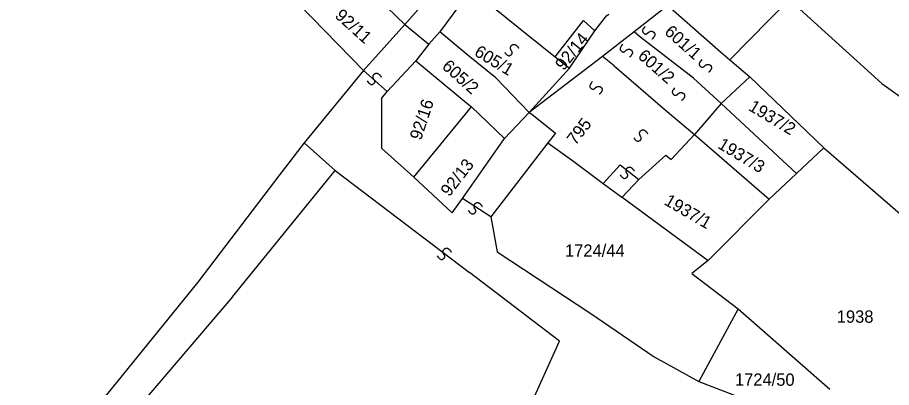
# Model space of a CAD drawing. Extents: x -581999 to -572728, y -1219553 to -1212032.
# Drawn here: x -578202.6 to -578061, y -1216054.7 to -1215994.7 of the extents above; entities that cross this region are included whole.
import ezdxf

# ---------------------------------------------------------------- set-up
doc = ezdxf.new("R2010")
doc.units = 0
for name, color, linetype in [('Vrstva 1', 7, 'Continuous'), ('Vrstva 2', 7, 'Continuous'), ('Vrstva 4', 7, 'Continuous'), ('Vrstva 6', 7, 'Continuous')]:
    doc.layers.add(name, color=color, linetype=linetype)

msp = doc.modelspace()

# ---------------------------------------------------------------- linework, layer by layer
at = {"layer": 'Vrstva 1'}
for p, q in [((-578139.851, -1215995.835), (-578135.956, -1215999.052)), ((-578115.453, -1216001.107), (-578110.864, -1215995.222)), ((-578110.864, -1215995.222), (-578109.045, -1215996.864)), ((-578101.772, -1215997.776), (-578102.681, -1215997.046)), ((-578093.044, -1216004.524), (-578101.772, -1215997.776)), ((-578116.469, -1216000.271), (-578115.453, -1216001.107)), ((-578115.453, -1216001.107), (-578113.167, -1216002.916)), ((-578105.92, -1216002.564), (-578107.772, -1216001.058)), ((-578088.547, -1216008.672), (-578093.044, -1216004.524)), ((-578119.665, -1216010.091), (-578119.228, -1216010.36)), ((-578119.228, -1216010.36), (-578115.409, -1216013.46)), ((-578115.409, -1216013.46), (-578116.637, -1216015.015)), ((-578151.137, -1216019.51), (-578156.158, -1216015.046)), ((-578116.637, -1216015.015), (-578113.054, -1216017.591)), ((-578076.346, -1216020.003), (-578071.932, -1216015.841)), ((-578113.054, -1216017.591), (-578112.637, -1216017.906)), ((-578112.637, -1216017.906), (-578107.7, -1216021.639)), ((-578167.767, -1216039.989), (-578151.137, -1216019.51)), ((-578080.759, -1216024.165), (-578076.346, -1216020.003))]:
    msp.add_line(p, q, dxfattribs=at)
for points in [[(-578129.074, -1215990.135), (-578134.141, -1215997.026)], [(-578136.492, -1215992.089), (-578139.851, -1215995.835)], [(-578126.956, -1215991.811), (-578121.41, -1215996.317), (-578116.469, -1216000.271)], [(-578077.566, -1215991.739), (-578087.158, -1216001.569)], [(-578077.566, -1215991.739), (-578062.548, -1216005.425), (-578049.109, -1216014.994)], [(-578146.526, -1216003.285), (-578157.002, -1215992.533)], [(-578097.19, -1215992.761), (-578102.681, -1215997.046), (-578107.772, -1216001.058), (-578119.665, -1216010.091)], [(-578097.19, -1215992.761), (-578088.663, -1216000.298)], [(-578113.167, -1216002.916), (-578109.045, -1215996.864), (-578107.154, -1215994.417), (-578106.766, -1215994.197)], [(-578139.851, -1215995.835), (-578146.526, -1216003.285)], [(-578134.141, -1215997.026), (-578135.956, -1215999.052), (-578138.064, -1216001.737)], [(-578129.569, -1216000.867), (-578134.141, -1215997.026)], [(-578088.663, -1216000.298), (-578087.158, -1216001.569)], [(-578143.599, -1216007.848), (-578142.684, -1216006.712), (-578138.064, -1216001.737)], [(-578138.064, -1216001.737), (-578129.492, -1216008.808)], [(-578125.094, -1216004.515), (-578129.569, -1216000.867)], [(-578087.158, -1216001.569), (-578083.919, -1216004.303)], [(-578146.526, -1216003.285), (-578156.158, -1216015.046), (-578160.105, -1216020.168), (-578173.391, -1216037.585)], [(-578119.665, -1216010.091), (-578113.167, -1216002.916)], [(-578105.92, -1216002.564), (-578097.627, -1216009.683)], [(-578125.094, -1216004.515), (-578119.665, -1216010.091)], [(-578083.919, -1216004.303), (-578088.547, -1216008.672)], [(-578083.919, -1216004.303), (-578071.932, -1216015.841)], [(-578143.599, -1216007.848), (-578143.612, -1216015.897), (-578138.374, -1216020.6)], [(-578129.492, -1216008.808), (-578129.012, -1216009.204)], [(-578088.547, -1216008.672), (-578092.882, -1216013.67)], [(-578088.547, -1216008.672), (-578076.346, -1216020.003)], [(-578138.374, -1216020.6), (-578129.012, -1216009.204)], [(-578129.012, -1216009.204), (-578123.677, -1216014.3)], [(-578123.677, -1216014.3), (-578119.665, -1216010.091)], [(-578097.627, -1216009.683), (-578092.882, -1216013.67)], [(-578138.374, -1216020.6), (-578132.185, -1216026.358), (-578130.501, -1216024.038), (-578123.677, -1216014.3)], [(-578097.519, -1216017.023), (-578096.678, -1216017.736), (-578092.882, -1216013.67)], [(-578092.882, -1216013.67), (-578080.759, -1216024.165)], [(-578116.637, -1216015.015), (-578125.894, -1216027.006), (-578124.847, -1216032.71), (-578109.683, -1216042.678), (-578099.436, -1216049.699), (-578092.185, -1216053.686)], [(-578071.932, -1216015.841), (-578041.233, -1216042.358)], [(-578101.891, -1216020.985), (-578097.519, -1216017.023)], [(-578107.7, -1216021.639), (-578104.655, -1216023.82), (-578104.621, -1216023.845)], [(-578101.891, -1216020.985), (-578104.621, -1216023.845)], [(-578104.621, -1216023.845), (-578090.677, -1216034.094)], [(-578080.759, -1216024.165), (-578090.677, -1216034.094)], [(-578090.677, -1216034.094), (-578093.321, -1216036.212), (-578085.808, -1216041.924)], [(-578173.391, -1216037.585), (-578196.969, -1216066.719), (-578202.608, -1216073.8)], [(-578167.767, -1216039.989), (-578196.405, -1216073.521)], [(-578085.808, -1216041.924), (-578092.185, -1216053.686)], [(-578085.808, -1216041.924), (-578070.933, -1216054.928)], [(-578092.185, -1216053.686), (-578072.802, -1216061.136)]]:
    msp.add_lwpolyline(points, dxfattribs=at)
at = {"layer": 'Vrstva 4'}
for p, q in [((-578146.526, -1216003.285), (-578142.684, -1216006.712)), ((-578151.137, -1216019.51), (-578129.325, -1216036.021)), ((-578125.894, -1216027.006), (-578130.501, -1216024.038))]:
    msp.add_line(p, q, dxfattribs=at)
for points in [[(-578142.679, -1215993.079), (-578139.851, -1215995.835)], [(-578107.7, -1216021.639), (-578104.922, -1216018.593), (-578101.891, -1216020.985)], [(-578119.764, -1216058.27), (-578114.787, -1216047.168), (-578129.325, -1216036.021)]]:
    msp.add_lwpolyline(points, dxfattribs=at)
at = {"layer": 'Vrstva 6'}
for points in [[(-578100.889, -1215996.168), (-578101.476, -1215996.79), (-578101.021, -1215997.399), (-578100.615, -1215997.387), (-578100.329, -1215997.082), (-578100.023, -1215996.928), (-578099.723, -1215996.944), (-578099.516, -1215997.046), (-578099.34, -1215997.249), (-578099.295, -1215997.613), (-578099.63, -1215998.125), (-578099.788, -1215998.217)], [(-578123.649, -1216000.331), (-578123.169, -1216001.038), (-578122.475, -1216000.727), (-578122.398, -1216000.327), (-578122.634, -1215999.982), (-578122.719, -1215999.65), (-578122.637, -1215999.36), (-578122.493, -1215999.18), (-578122.257, -1215999.052), (-578121.892, -1215999.088), (-578121.465, -1215999.527), (-578121.41, -1215999.7)], [(-578104.526, -1215999.086), (-578105.113, -1215999.708), (-578104.658, -1216000.317), (-578104.252, -1216000.305), (-578103.966, -1216000), (-578103.66, -1215999.846), (-578103.36, -1215999.862), (-578103.153, -1215999.964), (-578102.977, -1216000.167), (-578102.932, -1216000.531), (-578103.267, -1216001.043), (-578103.425, -1216001.135)], [(-578091.702, -1216001.542), (-578092.289, -1216002.164), (-578091.834, -1216002.773), (-578091.428, -1216002.761), (-578091.142, -1216002.456), (-578090.836, -1216002.302), (-578090.536, -1216002.318), (-578090.329, -1216002.42), (-578090.153, -1216002.623), (-578090.108, -1216002.987), (-578090.443, -1216003.499), (-578090.601, -1216003.591)], [(-578145.92, -1216005), (-578145.44, -1216005.707), (-578144.746, -1216005.396), (-578144.669, -1216004.996), (-578144.905, -1216004.651), (-578144.99, -1216004.319), (-578144.908, -1216004.029), (-578144.764, -1216003.849), (-578144.528, -1216003.721), (-578144.163, -1216003.757), (-578143.736, -1216004.196), (-578143.681, -1216004.369)], [(-578109.435, -1216005.105), (-578110.022, -1216005.727), (-578109.567, -1216006.336), (-578109.161, -1216006.324), (-578108.875, -1216006.019), (-578108.569, -1216005.865), (-578108.269, -1216005.881), (-578108.062, -1216005.983), (-578107.886, -1216006.186), (-578107.841, -1216006.55), (-578108.176, -1216007.062), (-578108.334, -1216007.154)], [(-578096.066, -1216006.102), (-578096.653, -1216006.724), (-578096.198, -1216007.333), (-578095.792, -1216007.321), (-578095.506, -1216007.016), (-578095.2, -1216006.862), (-578094.9, -1216006.878), (-578094.693, -1216006.98), (-578094.517, -1216007.183), (-578094.472, -1216007.547), (-578094.807, -1216008.059), (-578094.965, -1216008.151)], [(-578102.739, -1216014.191), (-578102.259, -1216014.898), (-578101.565, -1216014.587), (-578101.488, -1216014.187), (-578101.724, -1216013.842), (-578101.809, -1216013.51), (-578101.727, -1216013.22), (-578101.583, -1216013.04), (-578101.347, -1216012.912), (-578100.982, -1216012.948), (-578100.555, -1216013.387), (-578100.5, -1216013.56)], [(-578104.921, -1216020.21), (-578104.441, -1216020.917), (-578103.747, -1216020.606), (-578103.67, -1216020.206), (-578103.906, -1216019.861), (-578103.991, -1216019.529), (-578103.909, -1216019.239), (-578103.765, -1216019.059), (-578103.529, -1216018.931), (-578103.164, -1216018.967), (-578102.737, -1216019.406), (-578102.682, -1216019.579)], [(-578129.555, -1216025.973), (-578129.075, -1216026.68), (-578128.381, -1216026.369), (-578128.304, -1216025.969), (-578128.54, -1216025.624), (-578128.625, -1216025.292), (-578128.543, -1216025.002), (-578128.399, -1216024.822), (-578128.163, -1216024.694), (-578127.798, -1216024.73), (-578127.371, -1216025.169), (-578127.316, -1216025.342)], [(-578134.575, -1216033.353), (-578134.095, -1216034.06), (-578133.401, -1216033.749), (-578133.324, -1216033.349), (-578133.56, -1216033.004), (-578133.645, -1216032.672), (-578133.563, -1216032.382), (-578133.419, -1216032.202), (-578133.183, -1216032.074), (-578132.818, -1216032.11), (-578132.391, -1216032.549), (-578132.336, -1216032.722)]]:
    msp.add_open_spline(points, degree=2, dxfattribs=at)

# ---------------------------------------------------------------- texts
at = {"layer": 'Vrstva 2'}
for s, rotation, p in [('92/11', 317.93505, (-578151.297, -1215994.606)), ('601/1', 318.28442, (-578097.884, -1215997.243)), ('92/14', 50.93818, (-578114.103, -1216003.429)), ('605/1', 328.92286, (-578128.722, -1216000.777)), ('601/2', 318.28442, (-578102.208, -1216001.155)), ('605/2', 318.15336, (-578133.948, -1216002.834)), ('92/16', 71.74612, (-578137.202, -1216014.712)), ('1937/2', 328.926, (-578084.285, -1216009.644)), ('795', 52.2895, (-578112.176, -1216015.525)), ('1937/3', 328.926, (-578089.275, -1216015.781)), ('92/13', 52.01439, (-578132.636, -1216023.865)), ('1937/1', 329.65383, (-578097.948, -1216024.924))]:
    msp.add_text(s, height=2, rotation=rotation, dxfattribs=at).set_placement(p)
for s, p in [('1724/44', (-578113.877, -1216033.493)), ('1938', (-578069.827, -1216044.178)), ('1724/50', (-578086.33, -1216054.39))]:
    msp.add_text(s, height=2, dxfattribs=at).set_placement(p)

doc.saveas('drawing.dxf')
